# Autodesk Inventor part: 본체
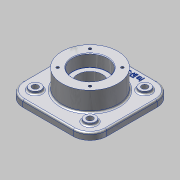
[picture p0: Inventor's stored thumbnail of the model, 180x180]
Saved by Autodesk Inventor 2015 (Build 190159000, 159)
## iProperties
Created: 2015-07
Part Number: 본체
Material: 알루미늄 6061
Document SubType Name: Modeling
Designer: AMC
Density: 2.7 g/cm^3
Appearance: 알루미늄 - 평지
Mass: 1459.27 g
Surface Area: 800.934 cm^2
Volume: 540.471 cm^3
Author: AMC
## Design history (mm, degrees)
sketch "스케치1"
  geometry: L1 (-75, -75)-(75, -75); L2 (75, -75)-(75, 75); L3 (75, 75)-(-75, 75); L4 (-75, 75)-(-75, -75); L5 (-75, -75)-(75, 75); L6 (75, -75)-(-75, 75); 1 further point
  constraints: 12 end point, 2 midpoint, 2 parallel, 1 horizontal, 1 perpendicular
  dimensions: "d0" = 150 distance of L3.end L2.end; "d1" = 150 distance of L2.end L1.end
extrude "돌출1" new body sketch "스케치1" distance "d2" = 12; taper "d3" = 0 deg
sketch "스케치2"
  geometry: C1 r 50 at (0, 0); 1 further point
  constraints: 1 centre point, 1 coincident
  dimensions: "d4" = 100 diameter of C1
extrude "돌출2" join sketch "스케치2" distance "d5" = 47; taper "d7" = 0 deg; dims "d6" = 23, "d8" = 0
sketch "스케치3"
  geometry: L1 (-75, 75)-(-75, -75) reference; L2 (75, -75)-(75, 75) reference; L3 (75, 75)-(-75, 75) reference; C1 r 10 at (-49, 49); C2 r 10 at (49, 49); C3 r 10 at (-49, -49); C4 r 10 at (49, -49); 1 further point
  constraints: 4 centre point, 2 vertical alignment, 1 horizontal alignment
  dimensions: "d9" = 20 diameter of C1; "d10" = 20 diameter of C2; "d11" = 20 diameter of C3; "d12" = 20 diameter of C4; "d13" = 26 distance from line of C1.centre L1; "d14" = 26 distance from line of C2.centre L2; "d15" = 98 distance of C2.centre C1.centre; "d16" = 98 distance of C4.centre C2.centre; "d17" = 26 distance from line of C2.centre L3
extrude "돌출3" join sketch "스케치3" distance "d18" = 5; taper "d19" = 0 deg
hole "구멍1" diameter "d22" = 11; stored, may be unused: countersink angle "d26" = 90 deg, drill point angle "d28" = 118 deg; dims "d20" = 10, "d21" = 10, "d23" = 6, "d24" = 4, "d25" = 2, "d27" = 8
hole "구멍2" diameter "d31" = 11; stored, may be unused: countersink angle "d35" = 90 deg, drill point angle "d37" = 118 deg; dims "d29" = 10, "d30" = 10, "d32" = 6, "d33" = 4, "d34" = 2, "d36" = 8
hole "구멍3" diameter "d40" = 11; stored, may be unused: countersink angle "d44" = 90 deg, drill point angle "d46" = 118 deg; dims "d38" = 10, "d39" = 10, "d41" = 6, "d42" = 4, "d43" = 2, "d45" = 8
hole "구멍4" diameter "d49" = 11; stored, may be unused: countersink angle "d53" = 90 deg, drill point angle "d55" = 118 deg; dims "d47" = 10, "d48" = 10, "d50" = 6, "d51" = 4, "d52" = 2, "d54" = 8
fillet "모깎기1" dims "d56" = 30
hole "구멍5" diameter "d59" = 45; stored, may be unused: countersink angle "d63" = 90 deg, drill point angle "d65" = 118 deg; dims "d57" = 10, "d58" = 10, "d60" = 6, "d61" = 62, "d62" = 22, "d64" = 8
hole "구멍6" diameter "d68" = 62; stored, may be unused: countersink angle "d72" = 90 deg, drill point angle "d74" = 0 deg; dims "d66" = 10, "d67" = 10, "d69" = 6, "d70" = 62, "d71" = 22, "d73" = 22
sketch "스케치4"
  geometry: L1 (0, 0)-(41, 0); L2 (0, 0)-(28.991, 28.991); A1 r 41 centre (0, 0) between (41, 0) and (28.991, 28.991); 1 further point
  constraints: 4 end point, 2 point on circle, 1 centre point, 1 coincident, 1 horizontal
  dimensions: "d75" = 82 diameter of A1; "d76" = 45 deg angle of L1 L2
hole "구멍7" sketch "스케치4" at (28.991, 28.991) diameter "d77" = 4.917; stored, may be unused: countersink angle "d81" = 90 deg, drill point angle "d83" = 118 deg; dims "d78" = 10, "d79" = 62, "d80" = 22, "d82" = 13
sketch "스케치5"
  geometry: L1 (0, 0)-(-41, 0); L2 (0, 0)-(-28.991, -28.991); A1 r 41 centre (0, 0) between (-41, 0) and (-28.991, -28.991); 1 further point
  constraints: 4 end point, 2 point on circle, 1 centre point, 1 coincident, 1 horizontal
  dimensions: "d87" = 82 diameter of A1; "d88" = 45 deg angle of L1 L2
hole "구멍8" sketch "스케치5" at (-28.991, -28.991) diameter "d89" = 4.917; stored, may be unused: countersink angle "d93" = 90 deg, drill point angle "d95" = 118 deg; dims "d90" = 10, "d91" = 62, "d92" = 22, "d94" = 13
fillet "모깎기2" dims "d99" = 0.3
chamfer "모따기1" distance "d100" = 1; stored, may be unused: second distance "d101" = 2, angle "d102" = 45 deg
sketch "스케치6"
  geometry: 2 further points
  constraints: 1 other
feature "엠보싱1" sketch "스케치6" dims "d0" = 150, "d1" = 150, "d103" = 1, "d104" = 0
fillet "모깎기3" dims "d105" = 3
fillet "모깎기4" dims "d106" = 3
fillet "모깎기5" dims "d107" = 3
node "솔리드1"
pattern_circular "원형 패턴1" dims angle "d85" = 360 deg
pattern_circular "원형 패턴2" dims angle "d97" = 360 deg
